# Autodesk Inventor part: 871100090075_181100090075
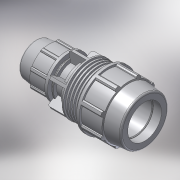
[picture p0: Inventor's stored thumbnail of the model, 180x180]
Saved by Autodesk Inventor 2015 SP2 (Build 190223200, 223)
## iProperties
Created: 2017-02
Part Number: 871100090075_181100090075
Material: PVC-Piping
Description: PLASSON REDUCING COUPLER 90-75
Document SubType Name: Modeling
Designer: KIM
Mass: 92.6774 g
Surface Area: 199.44 cm^2
Volume: 66.1981 cm^3
Density: 1.4 g/cm^3
Appearance: Smooth - White
Author: KIM
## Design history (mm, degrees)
derived "87110.ipt"
feature "Solid1::87110.ipt"
tag "TaggingFeature1"
body "Solid1"
other parameters: "d4" = 26.33333, "d5" = 45.14286, "d7" = 152, "d9" = 45.14286, "d11" = 4.51429, "d12" = 121.6, "d13" = 120 deg, "d14" = 126, "d15" = 6 deg, "d16" = 136.8, "d18" = 4.5, "d19" = 35 deg, "d20" = 17.5 deg, "d21" = 141.36, "d23" = 0, "d25" = 360 deg, "d27" = 3.04, "d42" = 69.52, "d46" = 1.8, "d51" = 316, "d52" = 45.14286, "d53" = 8 deg, "d54" = 169, "d56" = 105, "d57" = 75, "d58" = 81, "d59" = 67.5, "d60" = 118.8, "d61" = 105.6, "d62" = 39.5, "d63" = 56.88, "d64" = 120 deg, "d65" = 132, "d68" = 22.57143, "d74" = 122.76, "d75" = 35 deg, "d76" = 17.5 deg, "d78" = 0, "d80" = 360 deg, "d85" = 2.64, "d88" = 1.5, "d93" = 139, "d94" = 106.4, "d98" = 8.8, "d99" = 0, "d100" = 6.08, "d102" = 360 deg, "d104" = 2, "d106" = 0, "d107" = 8.8, "d108" = 0, "d109" = 8.8, "d110" = 0, "d111" = 2.98333, "d112" = 2.98333, "d113" = 2.98333, "d114" = 3.12514, "d116" = 3.12514, "d119" = 6.25029, "d125" = 134.064, "E_" = 152, "H_" = 316, "l_" = 169, "d_1" = 75, "E_1" = 132, "l_1" = 139, "d96" = 8.95, "d115" = 31.25143
